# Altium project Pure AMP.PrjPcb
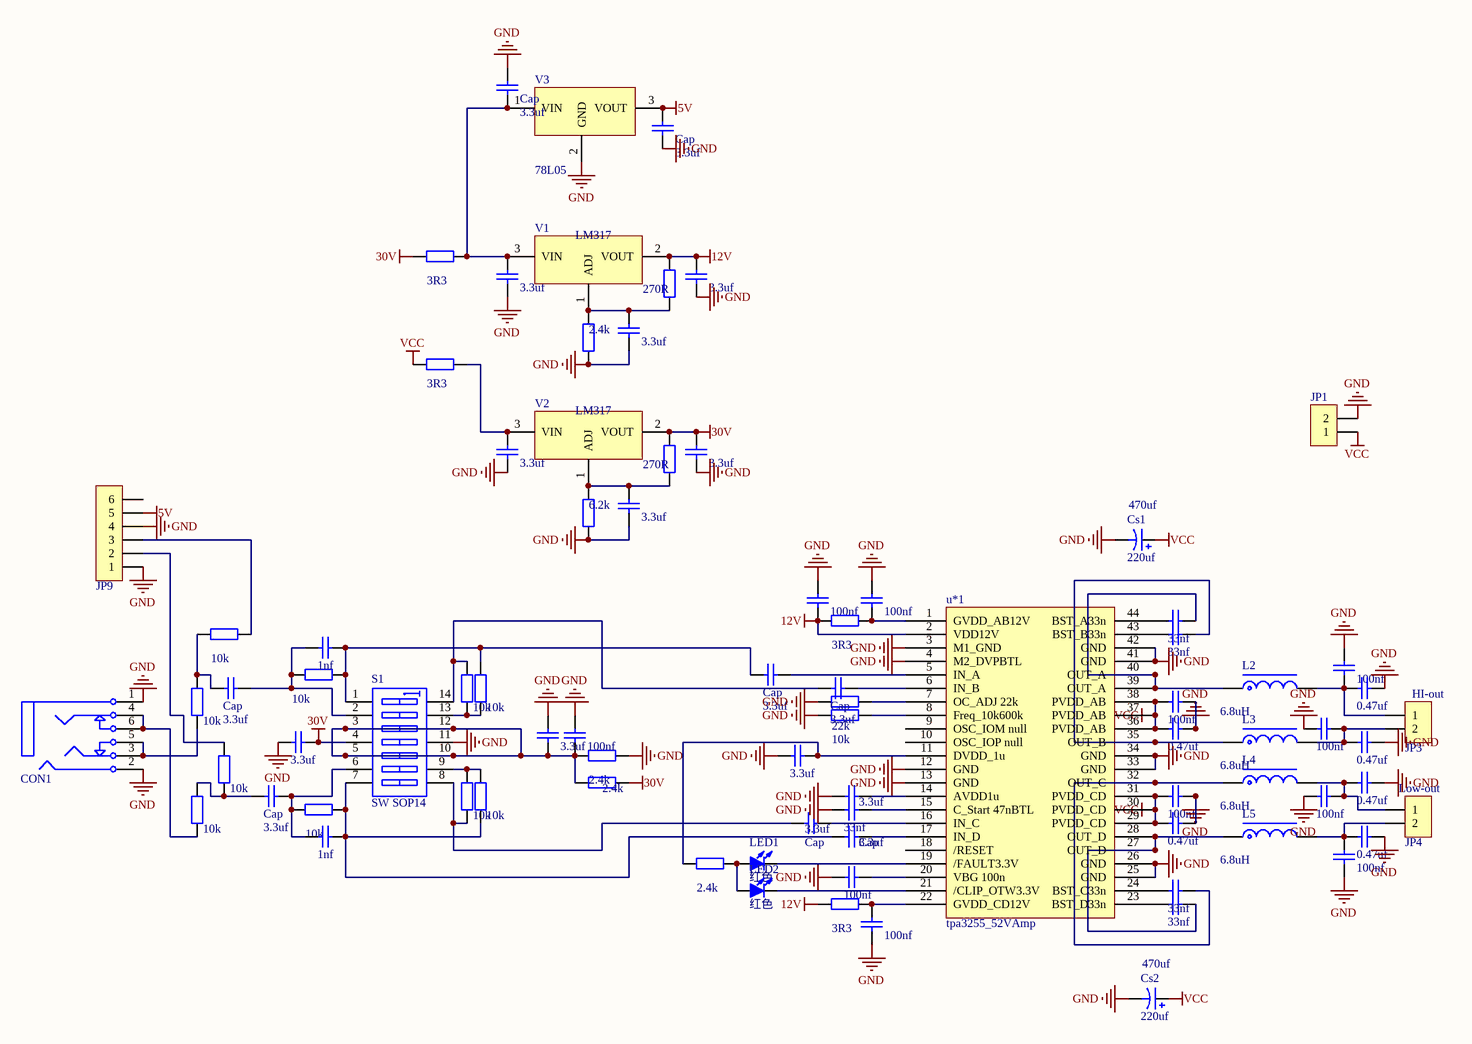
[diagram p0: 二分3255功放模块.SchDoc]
1 sheet, 83 parts. Net scope: global (net labels, ports and power ports of the same name join across sheets).
Board file: 3255PureAmP.PcbDoc

## Sheet 二分3255功放模块.SchDoc
size 381 x 241 mm

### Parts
C1  value 3.3uf  [C 0805]  (hidden comment: Cap)
C2  value 3.3uf  [C 0805]  (hidden comment: Cap)
C3  value 3.3uf  [C 0805]  (hidden comment: Cap)
C4  value 3.3uf  [C 0805]  (hidden comment: Cap)
C5  value 3.3uf  [C 0805]  (hidden comment: Cap)
C6  value 3.3uf  [C 0805]  (hidden comment: Cap)
C7  value 100nf  [C 0805]  (hidden comment: Cap)
C8  value 100nf  [C 0805]  (hidden comment: Cap)
C9  value 33nf  [C 0805]  (hidden comment: Cap)
C10  value 33nf  [C 0805]  (hidden comment: Cap)
C11  value 1nf  [C 0805]  (hidden comment: Cap)
C12  Cap  value 3.3uf  [C 0805]
C13  value 0.47uf  [C 0805]  (hidden comment: Cap)
C14  value 100nf  [C 0805]  (hidden comment: Cap)
C15  Cap  value 3.3uf  [C 0805]
C16  value 100nf  [C 0805]  (hidden comment: Cap)
C17  value 0.47uf  [C 0805]  (hidden comment: Cap)
C18  value 100nf  [C 0805]  (hidden comment: Cap)
C19  value 3.3uf  [C 0805]  (hidden comment: Cap)
C20  value 0.47uf  [C 0805]  (hidden comment: Cap)
C21  value 3.3uf  [C 0805]  (hidden comment: Cap)
C22  value 100nf  [C 0805]  (hidden comment: Cap)
C23  value 3.3uf  [C 0805]  (hidden comment: Cap)
C24  value 3.3uf  [C 0805]  (hidden comment: Cap)
C25  value 100nf  [C 0805]  (hidden comment: Cap)
C26  value 100nf  [C 0805]  (hidden comment: Cap)
C27  value 33nf  [C 0805]  (hidden comment: Cap)
C28  value 0.47uf  [C 0805]  (hidden comment: Cap)
C29  Cap  value 3.3uf  [C 0805]
C30  value 0.47uf  [C 0805]  (hidden comment: Cap)
C31  value 1nf  [C 0805]  (hidden comment: Cap)
C32  Cap  value 3.3uf  [C 0805]
C33  value 100nf  [C 0805]  (hidden comment: Cap)
C34  value 100nf  [C 0805]  (hidden comment: Cap)
C35  value 0.47uf  [C 0805]  (hidden comment: Cap)
C36  value 33nf  [C 0805]  (hidden comment: Cap)
C37  value 33nf  [C 0805]  (hidden comment: Cap)
C38  value 100nf  [C 0805]  (hidden comment: Cap)
C92  Cap  value 3.3uf  [C 0805]
C120  Cap  value 3.3uf  [C 0805]
C138  Cap  value 3.3uf  [C 0805]
C139  Cap  value 3.3uf  [C 0805]
CON1  PJ342  [PJ342A]  (value not drawn)
Cs1  220uf  value 470uf  [CAP 5.0*12.5*20]
Cs2  220uf  value 470uf  [CAP 5.0*12.5*20]
JP1  (no value)  [VH3.96-2P]
JP3  HI-out  [VH3.96-2P]
JP4  Low-out  [VH3.96-2P]
JP9  HDR-1X6  [HDR-1X6]  (value not drawn)
L2  value 6.8uH  [10*10]  (hidden comment: 10um)
L3  value 6.8uH  [10*10]  (hidden comment: 10um)
L4  value 6.8uH  [10*10]  (hidden comment: 10um)
L5  value 6.8uH  [10*10]  (hidden comment: 10um)
LED1  红色  [LED 0603B]
LED2  红色  [LED 0603B]
R1  value 270R  [R 0603]
R2  value 2.4k  [R 0603]
R3  value 270R  [R 0603]
R4  value 6.2k  [R 0603]
R5  value 3R3  [R 0603]
R6  value 10k  [R 0603]
R7  value 10k  [R 0603]
R8  value 10k  [R 0603]
R9  value 10k  [R 0603]
R10  value 22k  [R 0603]
R11  value 10k  [R 0603]
R12  value 2.4k  [R 0603]
R13  value 2.4k  [R 0603]
R14  value 10k  [R 0603]
R15  value 10k  [R 0603]
R16  value 10k  [R 0603]
R17  value 10k  [R 0603]
R18  value 2.4k  [R 0603]
R19  value 3R3  [R 0603]
R70  value 10k  [R 0603]
R79  value 3R3  [R 0603]
R80  value 3R3  [R 0603]
R700  value 10k  [R 0603]
S1  SW SOP14  [SOP14_NN]
u*1  tpa3255_52VAmp  [3255_TSSOP-44]
V1  LM317  [SOT223_N]
V2  LM317  [SOT223_N]
V3  78L05  [SOT89_N]

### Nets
5V: C138.2 JP9.5 V3.3(VOUT)
12V: C2.2 C7.1 R1.1 R5.2 R19.2 u*1.2(VDD12V) V1.2(VOUT)
30V: C5.2 C19.2 R3.1 R13.2 R79.2 S1.4(A4) V2.2(VOUT)
GND: C1.2 C2.1 C3.2 C4.2 C5.1 C6.2 C7.2 C8.2 C13.1 C14.1 C16.2 C17.2 C18.2 C19.1 C20.1 C21.2 C22.2 C23.1 C24.2 C25.2 C26.2 C27.2 C28.1 C30.2 C33.2 C34.2 C35.2 C38.1 C138.1 C139.1 CON1.1 CON1.2 Cs1.2 Cs2.2 JP1.2 JP9.1 JP9.4 R2.2 R4.2 R10.2 R11.2 R12.2 S1.11(B4) u*1.3(M1_GND) u*1.4(M2_DVPBTL) u*1.12(GND) u*1.13(GND) u*1.25(GND) u*1.26(GND) u*1.33(GND) u*1.34(GND) u*1.41(GND) u*1.42(GND) V3.2(GND)
VCC: C16.1 C17.1 C25.1 C30.1 Cs1.1 Cs2.1 JP1.1 R80.2 u*1.29(PVDD_CD) u*1.30(PVDD_CD) u*1.31(PVDD_CD) u*1.36(PVDD_AB) u*1.37(PVDD_AB) u*1.38(PVDD_AB)
NetC1_1: C1.1 C139.2 R79.1 V1.3(VIN) V3.1(VIN)
NetC3_1: C3.1 R1.2 R2.1 V1.1(ADJ)
NetC4_1: C4.1 R80.1 V2.3(VIN)
NetC6_1: C6.1 R3.2 R4.1 V2.1(ADJ)
NetC8_1: C8.1 R5.1 u*1.1(GVDD_AB12V)
NetC9_1: C9.1 u*1.44(BST_A33n)
NetC9_2: C9.2 L2.1 u*1.39(OUT_A) u*1.40(OUT_A)
NetC10_1: C10.1 u*1.43(BST_B33n)
NetC10_2: C10.2 L3.1 u*1.35(OUT_B)
NetC11_1: C11.1 C120.2 R6.2 S1.2(A2)
NetC11_2: C11.2 C12.1 R6.1 R9.1 S1.1(A1)
NetC12_2: C12.2 u*1.5(IN_A)
NetC13_2: C13.2 C14.2 JP3.1 L2.2
NetC15_1: C15.1 R8.1 S1.14(B1)
NetC15_2: C15.2 u*1.6(IN_B)
NetC18_1: C18.1 C20.2 JP3.2 L3.2
NetC21_1: C21.1 C22.1 R12.1 R13.1 S1.3(A3) S1.5(A5) S1.10(B5) S1.12(B3)
NetC23_2: C23.2 R18.2 u*1.11(DVDD_1u)
NetC24_1: C24.1 u*1.14(AVDD1u)
NetC26_1: C26.1 C28.2 JP4.1 L4.2
NetC27_1: C27.1 u*1.15(C_Start_47nBTL)
NetC29_1: C29.1 R15.2 S1.8(B7)
NetC29_2: C29.2 u*1.16(IN_C)
NetC31_1: C31.1 C92.1 R17.2 S1.6(A6)
NetC31_2: C31.2 C32.1 R16.2 R17.1 S1.7(A7)
NetC32_2: C32.2 u*1.17(IN_D)
NetC33_1: C33.1 C35.1 JP4.2 L5.2
NetC34_1: C34.1 u*1.20(VBG_100n)
NetC36_1: C36.1 u*1.24(BST_C33n)
NetC36_2: C36.2 L4.1 u*1.32(OUT_C)
NetC37_1: C37.1 u*1.23(BST_D33n)
NetC37_2: C37.2 L5.1 u*1.27(OUT_D) u*1.28(OUT_D)
NetC38_2: C38.2 R19.1 u*1.22(GVDD_CD12V)
NetC92_2: C92.2 R14.1 R70.2
NetC120_1: C120.1 R7.1 R700.1
NetCON1_3: CON1.3 CON1.5 R7.2
NetCON1_4: CON1.4 CON1.6 R14.2
NetJP9_2: JP9.2 R70.1
NetJP9_3: JP9.3 R700.2
NetLED1_1: LED1.1(A) LED2.1(A) R18.1
NetLED1_2: LED1.2(K) u*1.19(/FAULT3.3V)
NetLED2_2: LED2.2(K) u*1.21(/CLIP_OTW3.3V)
NetR8_2: R8.2 R9.2 S1.13(B2)
NetR10_1: R10.1 u*1.7(OC_ADJ_22k)
NetR11_1: R11.1 u*1.8(Freq_10k600k)
NetR15_1: R15.1 R16.1 S1.9(B6)

Not connected (* = marked no-connect by the designer): JP9 6; u*1 9(OSC_IOM_null) 10(OSC_IOP_null) 18(/RESET)

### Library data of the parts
C1-C38 C92 C120 C138 C139 = Cap: Capacitor
CON1 = PJ342: 3.5耳机插座,4Pin; BOM名称: 耳机插座; 版权归属: 源创客
Cs1 Cs2 = Cap Pol1: Polarized Capacitor (Radial)
JP1 = Header 2: 2P接插件; 版权归属: 源创客; Value: VH3.96
JP3 JP4 = Header 2: 2P接插件; 版权归属: 源创客
JP9 = Header 6: 6P接插件; 版权归属: 源创客
L2-L5 = L-CD: 贴片功率电感; BOM名称: 功率电感; 版权归属: 源创客
LED1 LED2 = LED-SMD: 贴片LED; 版权归属: 源创客
R1-R19 R70 R79 R80 R700 = Res2: 贴片电阻
S1 = SW DIP-7: DIP Switch, 7 Position, SPST; Value: TL074
u*1 = tpa3255: TPA3251
V1 V2 = LM317: 可调线性稳压芯片; 版权归属: 源创客
V3 = 78Mxx: BOM名称: 线性稳压芯片; 版权归属: 源创客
